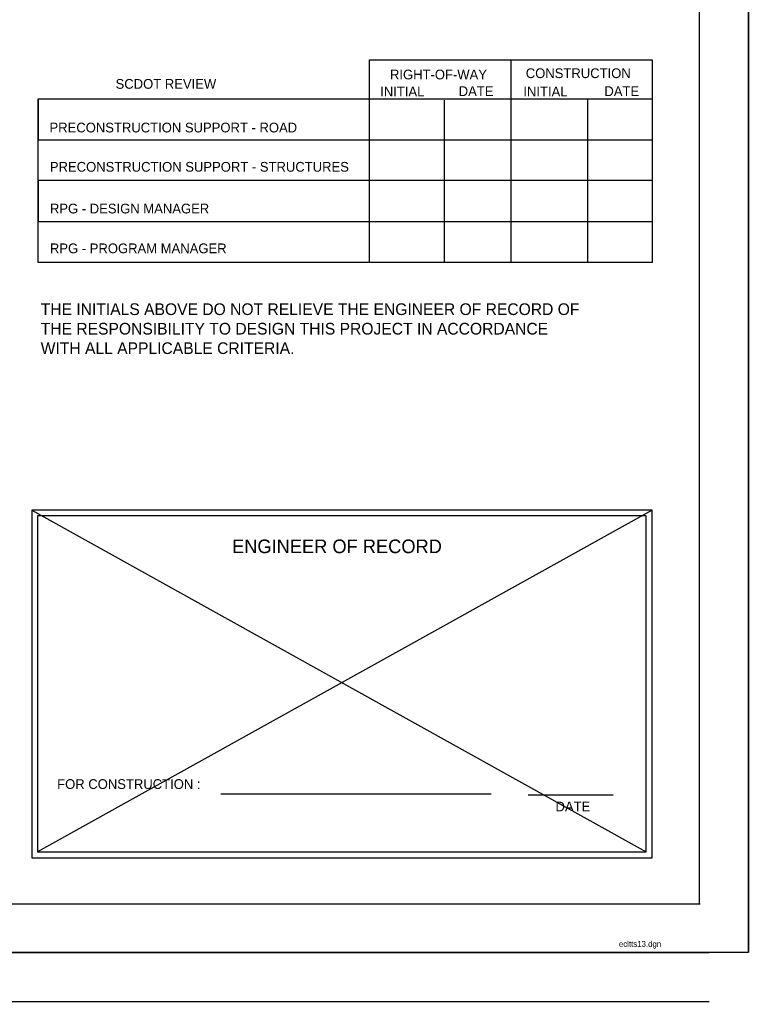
# Model space of a CAD drawing. Extents: x 1524103 to 2096450, y 1024229 to 1162569.
# Drawn here: x 2075511 to 2091305, y 1113991 to 1135259 of the extents above; entities that cross this region are included whole.
import ezdxf

# ---------------------------------------------------------------- set-up
doc = ezdxf.new("R2010")
doc.units = 0
for name, color, linetype in [('RD_SHT_Bndy', 7, 'Continuous'), ('RD_SHT_IplotShp', 7, 'Continuous'), ('RD_SHT_Snap', 7, 'Continuous'), ('RD_SHT_TX', 7, 'Continuous')]:
    doc.layers.add(name, color=color, linetype=linetype)

msp = doc.modelspace()

# ---------------------------------------------------------------- linework, layer by layer
at = {"layer": 'RD_SHT_Bndy'}
for p, q in [((2090249, 1116103), (2090249, 1160459)), ((2083093, 1129997), (2083093, 1134390)), ((2083093, 1134390), (2089218, 1134390)), ((2086156, 1134390), (2086156, 1129997)), ((2089218, 1134390), (2089218, 1129997)), ((2075912, 1129997), (2075912, 1133545)), ((2075912, 1133545), (2089218, 1133545)), ((2075912, 1133545), (2075912, 1132658)), ((2084709, 1133518), (2084709, 1129997)), ((2087818, 1133539), (2087818, 1129997)), ((2075912, 1132658), (2089218, 1132658)), ((2089218, 1132658), (2089218, 1131771)), ((2089218, 1131771), (2075912, 1131771)), ((2075912, 1131771), (2075912, 1130884)), ((2075912, 1130884), (2089218, 1130884)), ((2089218, 1130884), (2089218, 1129997)), ((2089218, 1129997), (2075912, 1129997)), ((2075775, 1124635), (2089092, 1117228)), ((2089218, 1124635), (2075901, 1117228)), ((2079872, 1118486), (2085729, 1118486)), ((2086536, 1118462), (2088372, 1118462)), ((2019473, 1116103), (2090264, 1116103)), ((2016109, 1115047), (2090454, 1115047)), ((2016109, 1113991), (2090454, 1113991))]:
    msp.add_line(p, q, dxfattribs=at)
for points in [[(2075775, 1117101), (2089218, 1117101), (2089218, 1124635), (2075775, 1124635)], [(2075901, 1117228), (2089092, 1117228), (2089092, 1124508), (2075901, 1124508)]]:
    msp.add_lwpolyline(points, close=True, dxfattribs=at)
at = {"layer": 'RD_SHT_IplotShp'}
msp.add_lwpolyline([(2015439, 1161513), (2091301, 1161513), (2091301, 1115047), (2015439, 1115047)], close=True, dxfattribs=at)
at = {"layer": 'RD_SHT_Snap'}
msp.add_line((2091305, 1161513), (2091305, 1115047), dxfattribs=at)

# ---------------------------------------------------------------- texts
at = {"layer": 'RD_SHT_TX'}
for s, height, p in [('RIGHT-OF-WAY', 211.21, (2083538, 1133965)), ('CONSTRUCTION', 211.21, (2086481, 1133993)), ('SCDOT REVIEW', 211.21, (2077591, 1133762)), ('INITIAL', 211.2, (2083326, 1133595)), ('DATE', 211.2, (2085028, 1133604)), ('INITIAL', 211.2, (2086429, 1133595)), ('DATE', 211.2, (2088185, 1133604)), ('PRECONSTRUCTION SUPPORT - ROAD', 211.21, (2076159, 1132816)), ('PRECONSTRUCTION SUPPORT - STRUCTURES', 211.21, (2076167, 1131965)), ('RPG - DESIGN MANAGER', 211.21, (2076168, 1131061)), ('RPG - PROGRAM MANAGER', 211.21, (2076168, 1130199)), ('THE INITIALS ABOVE DO NOT RELIEVE THE ENGINEER OF RECORD OF ', 253.45, (2075968, 1128860)), ('THE RESPONSIBILITY TO DESIGN THIS PROJECT IN ACCORDANCE ', 253.45, (2075968, 1128437)), ('WITH ALL APPLICABLE CRITERIA.', 253.45, (2075968, 1128015)), ('ENGINEER OF RECORD', 295.69, (2080115, 1123701)), ('FOR CONSTRUCTION :', 211.21, (2076325, 1118593)), ('DATE', 211.2, (2087125, 1118107)), ('ecltts13.dgn', 126.73, (2088501, 1115172))]:
    msp.add_text(s, height=height, dxfattribs=at).set_placement(p)

doc.saveas('drawing.dxf')
